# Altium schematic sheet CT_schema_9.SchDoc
size 391 x 238 mm
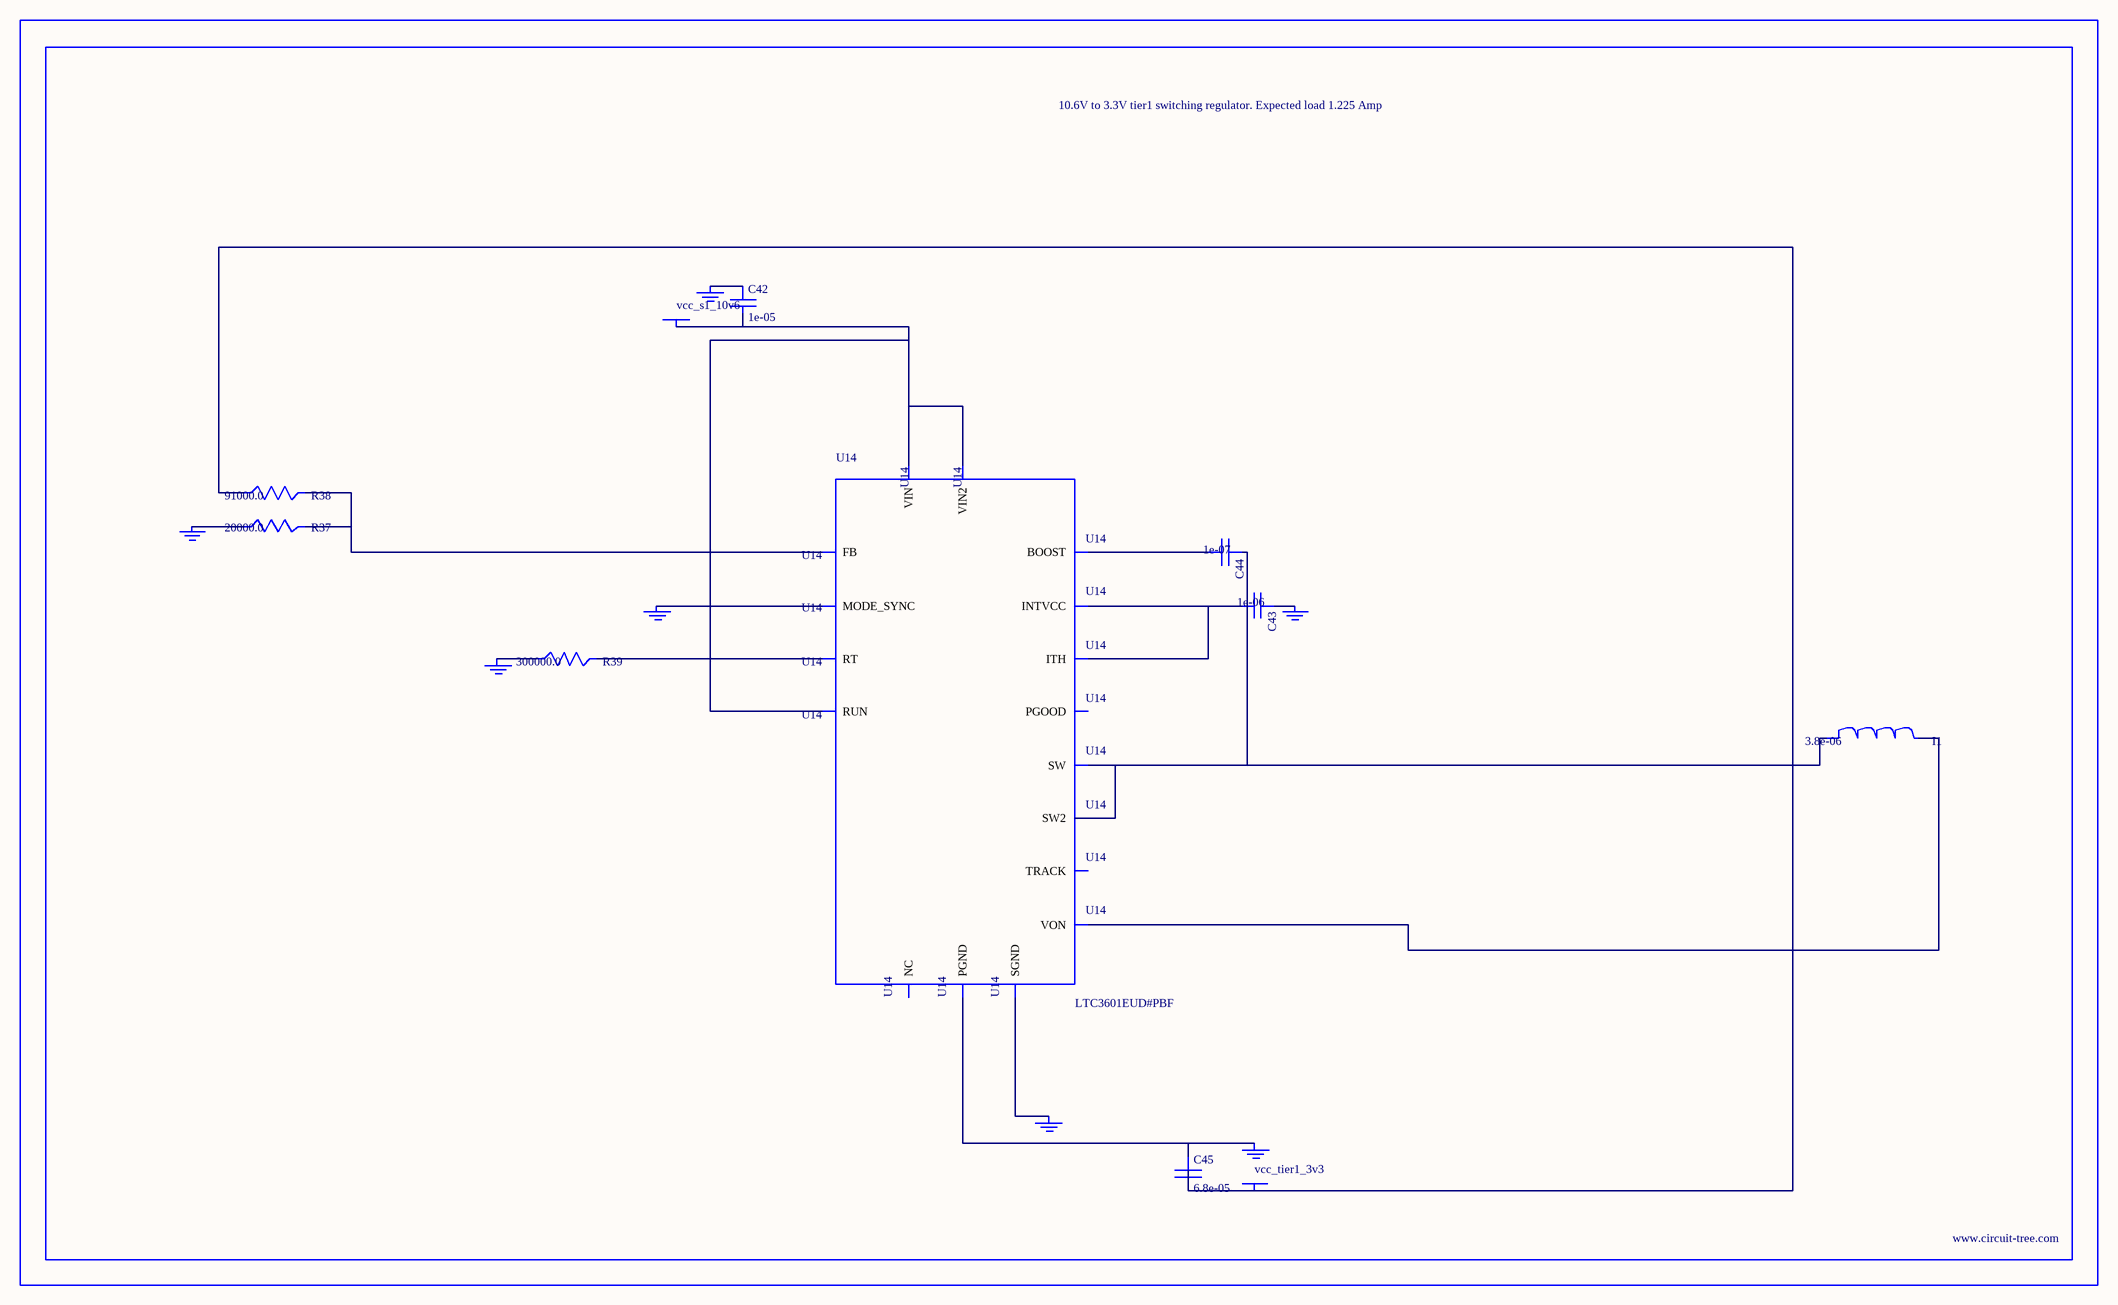
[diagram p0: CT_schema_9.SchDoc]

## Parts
BORDER8  (no value)
C42  1e-05  [C0805]
C43  1e-06  [C0603]
C44  1e-07  [C0402]
C45  6.8e-05  [2220]
GND_INSTANCE_8_0  (no value)
GND_INSTANCE_8_1  (no value)
GND_INSTANCE_8_2  (no value)
GND_INSTANCE_8_3  (no value)
GND_INSTANCE_8_4  (no value)
GND_INSTANCE_8_5  (no value)
GND_INSTANCE_8_6  (no value)
I1  3.8e-06  [DR1040]
POWER_INSTANCE_8_0  vcc_s1_10v6
POWER_INSTANCE_8_1  vcc_tier1_3v3
R37  20000.0  [R0603]
R38  91000.0  [R0603]
R39  300000.0  [R0603]
U14  LTC3601EUD#PBF  [QFN-16_EP]

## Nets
NetC42_1: C42.1 GND_INSTANCE_8_5.0(GND)
NetC42_2: C42.2 POWER_INSTANCE_8_0.0(PWR) U14.14(RUN) U14.15(VIN) U14.16(VIN2)
NetC43_1: C43.1 GND_INSTANCE_8_1.0(GND)
NetC43_2: C43.2 U14.7(INTVCC) U14.12(ITH)
NetC44_1: C44.1 I1.1 U14.3(SW) U14.4(SW2)
NetC44_2: C44.2 U14.6(BOOST)
NetC45_1: C45.1 GND_INSTANCE_8_6.0(GND) U14.17(PGND)
NetC45_2: C45.2 I1.2 POWER_INSTANCE_8_1.0(PWR) R38.1 U14.8(VON)
NetGND_INSTANCE_8_0_0: GND_INSTANCE_8_0.0(GND) U14.1(MODE_SYNC)
NetGND_INSTANCE_8_2_0: GND_INSTANCE_8_2.0(GND) U14.9(SGND)
NetGND_INSTANCE_8_3_0: GND_INSTANCE_8_3.0(GND) R39.1
NetGND_INSTANCE_8_4_0: GND_INSTANCE_8_4.0(GND) R37.1
NetR37_2: R37.2 R38.2 U14.11(FB)
NetR39_2: R39.2 U14.10(RT)

Not connected (* = marked no-connect by the designer): U14 2(PGOOD) 5(NC) 13(TRACK)

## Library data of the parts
BORDER8 = BORDER_PAGE8
C42 = C0805C106K8RACTU
C43 = C0603C105K3RACTU
C44 = C0402C104K3RACTU
C45 = C5750X5R1A686M
GND_INSTANCE_8_0-GND_INSTANCE_8_6 = GND
I1 = DR1040-3R8-R
POWER_INSTANCE_8_0 POWER_INSTANCE_8_1 = PWR
R37 = RC0603JR-0720KL
R38 = RC0603JR-0791KL
R39 = RC0603JR-07300KL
